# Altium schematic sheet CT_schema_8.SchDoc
size 147 x 119 mm
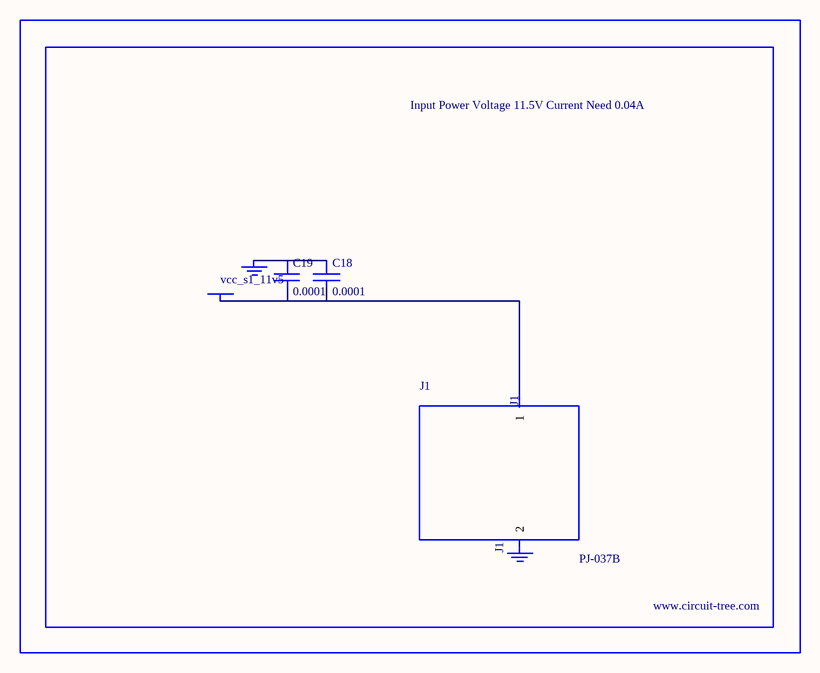
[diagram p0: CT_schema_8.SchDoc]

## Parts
BORDER7  (no value)
C18  0.0001  [EXV-9H]
C19  0.0001  [EXV-9H]
GND_INSTANCE_7_0  (no value)
GND_INSTANCE_7_1  (no value)
J1  PJ-037B  [PJ-037B_PACKAGE]
POWER_INSTANCE_7_0  vcc_s1_11v5

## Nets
NetC18_1: C18.1 C19.1 GND_INSTANCE_7_0.0(GND)
NetC18_2: C18.2 C19.2 J1.1 POWER_INSTANCE_7_0.0(PWR)

Not connected (* = marked no-connect by the designer): GND_INSTANCE_7_1 0(GND); J1 2

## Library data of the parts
BORDER7 = BORDER_PAGE7
C18 C19 = EDK107M035A9HAA
GND_INSTANCE_7_0 GND_INSTANCE_7_1 = GND
POWER_INSTANCE_7_0 = PWR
